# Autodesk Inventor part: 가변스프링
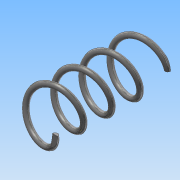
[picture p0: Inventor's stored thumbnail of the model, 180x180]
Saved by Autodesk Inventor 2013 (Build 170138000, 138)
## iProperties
Created: 2015-09
Part Number: 가변스프링
Material: 강철, 탄소
Document SubType Name: Modeling
Designer: Administrator
Mass: 4.92088 g
Surface Area: 12.7468 cm^2
Volume: 0.625271 cm^3
Density: 7.87 g/cm^3
Author: Administrator
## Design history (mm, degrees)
sketch "스케치1"
  geometry: L1 (0, 0)-(0, 42); L2 (0, 0)-(8, 0); L3 (0, 42)-(8, 42); C1 r 1 at (8, 0)
  constraints: 6 end point, 1 centre point, 1 horizontal alignment, 1 parallel, 1 perpendicular, 1 vertical
  dimensions: "d0" = 42 distance of L1.start L1.end (derived); "d1" = 2 diameter of C1; "d2" = 16 diameter of L2.end L1; "d3" = 8 distance of L1.end L3.end
feature "코일1" sketch "스케치1" pitch "d4" = 10; turns "d6" = 4; dims "d5" = 42 (= d0), "d7" = 0, angle "d8" = 90 deg, angle "d9" = 90 deg, "d10" = 0, "d11" = 0
sketch "스케치2"
  geometry: L1 (42, 10)-(0, 10); L2 (0, 10)-(0, -10); L3 (0, -10)-(42, -10); L4 (42, -10)-(42, 10); 2 further points
  constraints: 8 end point, 2 parallel, 1 coincident, 1 horizontal, 1 midpoint, 1 perpendicular
  dimensions: "d12" = 20 distance of L3.end L1.start; "d14" = 42 distance of L1.start L1.end (derived)
extrude "돌출1" sketch "스케치2" stored distance "d15" = 10; taper "d16" = 0 deg
node "솔리드1"
